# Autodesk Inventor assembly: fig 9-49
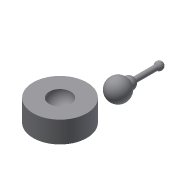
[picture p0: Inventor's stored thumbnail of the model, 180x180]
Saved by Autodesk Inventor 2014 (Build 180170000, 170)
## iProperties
Created: 2013-07
Part Number: fig 9-49
Document SubType Name: Assembly
Designer: CADCIM
Author: CADCIM
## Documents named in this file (3)
- E:\APS\Autodesk Inventor 2014-Project\inventor_2014_partfiles\Inventor_2014_prt\c09_Inv_2014_prt\c09_inv_2014_prt\fig 9-49.iam
- E:\APS\c09partfile\fig 9-49_1.ipt
- E:\APS\c09partfile\fig 9-49_2.ipt
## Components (2 placed, 2 different names)
1. fig 9-49_1:1
2. fig 9-49_2:1
